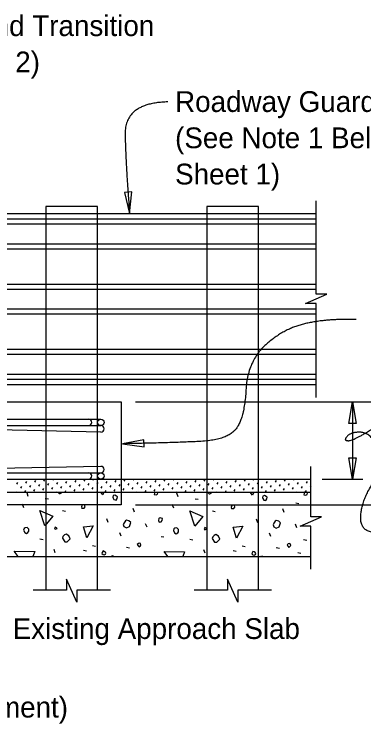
# Model space of a CAD drawing. Extents: x 0 to 41.1, y 0 to 26.
# Drawn here: x 32.17 to 35.56, y 8.63 to 15.52 of the extents above; entities that cross this region are included whole.
import ezdxf

# ---------------------------------------------------------------- set-up
doc = ezdxf.new("R2010")
doc.units = 0
for name, color, linetype in [('Dimension', 7, 'Continuous'), ('Miscellaneous', 7, 'Continuous'), ('Rebar', 7, 'Continuous'), ('TextStructures', 7, 'Continuous'), ('TrafBarrierConc', 7, 'Continuous')]:
    doc.layers.add(name, color=color, linetype=linetype)

# ---------------------------------------------------------------- blocks, each defined once
blk = doc.blocks.new('Terminator-Arrow')
at = {"layer": 'Dimension'}
blk.add_lwpolyline([(0, 0), (-0.00041, 0.000069), (-0.00041, -0.000069)], close=True, dxfattribs=at)

msp = doc.modelspace()

# ---------------------------------------------------------------- linework, layer by layer
at = {"layer": 'Dimension'}
for p, q in [((33.3449, 11.758), (36.4484, 11.758)), ((35.4495, 11.7581), (35.4495, 11.008)), ((35.1545, 11.008), (35.5492, 11.008)), ((33.3449, 10.758), (36.4484, 10.758))]:
    msp.add_line(p, q, dxfattribs=at)
for points in [[(33.2871, 13.5874), (33.3079, 13.7976), (33.2375, 13.7927)], [(33.2182, 11.3529), (33.427, 11.3211), (33.4259, 11.3916)]]:
    msp.add_lwpolyline(points, close=True, dxfattribs=at)
for points in [[(35.096, 11.8029), (35.096, 12.7141), (34.9927, 12.7141), (35.096, 12.7591), (35.1994, 12.8041), (35.096, 12.8041), (35.096, 13.713)], [(35.0443, 10.133), (35.0443, 10.5512), (34.941, 10.5512), (35.0443, 10.5962), (35.1476, 10.6412), (35.0443, 10.6412), (35.0443, 11.133)], [(33.1003, 9.9291), (32.775, 9.9291), (32.775, 9.8128), (32.6756, 10.0378), (32.6756, 9.9291), (32.3503, 9.9291)], [(34.6628, 9.9291), (34.3375, 9.9291), (34.3375, 9.8128), (34.2381, 10.0378), (34.2381, 9.9291), (33.9128, 9.9291)]]:
    msp.add_lwpolyline(points, dxfattribs=at)
for points in [[(33.6564, 14.6721), (33.2351, 14.6614), (33.2506, 14.042), (33.2871, 13.5874)], [(35.484, 12.5597), (35.1842, 12.5665), (34.7731, 12.4653), (34.4306, 12.1511), (34.4007, 11.5994), (34.2351, 11.3881), (33.6875, 11.3607), (33.2182, 11.3528)], [(35.6803, 10.4905), (35.5295, 10.4905), (35.5295, 10.7717), (35.7077, 11.0735), (35.7077, 11.293), (35.6049, 11.4645), (35.4335, 11.4645), (35.3582, 11.3822), (35.461, 11.3822), (35.6323, 11.492)]]:
    msp.add_open_spline(points, degree=2, dxfattribs=at)
at = {"layer": 'Miscellaneous'}
for p, q in [((27.9244, 13.588), (35.096, 13.588)), ((28.582, 13.5358), (35.096, 13.5358)), ((28.5832, 13.4876), (35.096, 13.4876)), ((28.5879, 13.2948), (35.096, 13.2948)), ((28.5891, 13.2465), (35.096, 13.2465)), ((28.5856, 12.9026), (35.096, 12.9026)), ((28.5844, 12.8543), (35.096, 12.8543)), ((28.575, 12.6134), (35.096, 12.6134)), ((28.5792, 12.6615), (35.096, 12.6615)), ((28.5891, 12.2695), (35.096, 12.2695)), ((28.5879, 12.2212), (35.096, 12.2212)), ((28.5817, 12.0284), (35.096, 12.0284)), ((27.9244, 11.9279), (35.096, 11.9279)), ((28.5827, 11.9802), (35.096, 11.9802)), ((32.1932, 10.9594), (32.2029, 10.9762)), ((32.2807, 10.9691), (32.2904, 10.9859)), ((32.3682, 10.9788), (32.3779, 10.9956)), ((32.4557, 10.9885), (32.4654, 11.0053)), ((32.4946, 10.9496), (32.5043, 10.9664)), ((32.5432, 10.9983), (32.5488, 11.008)), ((32.5821, 10.9594), (32.5918, 10.9762)), ((32.6696, 10.9691), (32.6793, 10.9859)), ((32.7571, 10.9788), (32.7668, 10.9956)), ((32.8446, 10.9885), (32.8543, 11.0053)), ((32.8835, 10.9496), (32.8932, 10.9664)), ((32.9321, 10.9983), (32.9377, 11.008)), ((32.971, 10.9594), (32.9807, 10.9762)), ((33.0585, 10.9691), (33.0682, 10.9859)), ((33.146, 10.9788), (33.1557, 10.9956)), ((33.2335, 10.9885), (33.2432, 11.0053)), ((33.2724, 10.9496), (33.2821, 10.9664)), ((33.321, 10.9983), (33.3266, 11.008)), ((33.3599, 10.9594), (33.3696, 10.9762)), ((33.4474, 10.9691), (33.4571, 10.9859)), ((33.5349, 10.9788), (33.5446, 10.9956)), ((33.6224, 10.9885), (33.6321, 11.0053)), ((33.6613, 10.9496), (33.671, 10.9664)), ((33.7099, 10.9983), (33.7156, 11.008)), ((33.7488, 10.9594), (33.7585, 10.9762)), ((33.8363, 10.9691), (33.846, 10.9859)), ((33.9238, 10.9788), (33.9336, 10.9956)), ((34.0113, 10.9885), (34.0211, 11.0053)), ((34.0502, 10.9496), (34.0599, 10.9664)), ((34.0988, 10.9983), (34.1045, 11.008)), ((34.1377, 10.9594), (34.1475, 10.9762)), ((34.2252, 10.9691), (34.235, 10.9859)), ((34.3127, 10.9788), (34.3225, 10.9956)), ((34.4002, 10.9885), (34.41, 11.0053)), ((34.4391, 10.9496), (34.4489, 10.9664)), ((34.4877, 10.9983), (34.4934, 11.008)), ((34.5266, 10.9594), (34.5364, 10.9762)), ((34.6141, 10.9691), (34.6239, 10.9859)), ((34.7016, 10.9788), (34.7114, 10.9956)), ((34.7892, 10.9885), (34.7989, 11.0053)), ((34.828, 10.9496), (34.8378, 10.9664)), ((34.8767, 10.9983), (34.8823, 11.008)), ((34.9155, 10.9594), (34.9253, 10.9762)), ((35.0031, 10.9691), (35.0128, 10.9859)), ((32.1899, 10.883), (32.1932, 10.8887)), ((32.2321, 10.9205), (32.2418, 10.9373)), ((32.2718, 10.883), (32.2807, 10.8984)), ((32.3196, 10.9302), (32.3293, 10.947)), ((32.3585, 10.8913), (32.3682, 10.9081)), ((32.4071, 10.9399), (32.4168, 10.9567)), ((32.446, 10.901), (32.4557, 10.9178)), ((32.5335, 10.9108), (32.5432, 10.9275)), ((32.5788, 10.883), (32.5821, 10.8887)), ((32.621, 10.9205), (32.6307, 10.9373)), ((32.6607, 10.883), (32.6696, 10.8984)), ((32.7085, 10.9302), (32.7182, 10.947)), ((32.7474, 10.8913), (32.7571, 10.9081)), ((32.796, 10.9399), (32.8057, 10.9567)), ((32.8349, 10.901), (32.8446, 10.9178)), ((32.9224, 10.9108), (32.9321, 10.9275)), ((32.9677, 10.883), (32.971, 10.8887)), ((33.0099, 10.9205), (33.0196, 10.9373)), ((33.0496, 10.883), (33.0585, 10.8984)), ((33.0974, 10.9302), (33.1071, 10.947)), ((33.1363, 10.8913), (33.146, 10.9081)), ((33.1849, 10.9399), (33.1946, 10.9567)), ((33.2238, 10.901), (33.2335, 10.9178)), ((33.3113, 10.9108), (33.321, 10.9275)), ((33.3566, 10.883), (33.3599, 10.8887)), ((33.3988, 10.9205), (33.4085, 10.9373)), ((33.4385, 10.883), (33.4474, 10.8984)), ((33.4863, 10.9302), (33.496, 10.947)), ((33.5252, 10.8913), (33.5349, 10.9081)), ((33.5738, 10.9399), (33.5835, 10.9567)), ((33.6127, 10.901), (33.6224, 10.9178)), ((33.7002, 10.9108), (33.7099, 10.9275)), ((33.7455, 10.883), (33.7488, 10.8887)), ((33.7877, 10.9205), (33.7974, 10.9373)), ((33.8274, 10.883), (33.8363, 10.8984)), ((33.8752, 10.9302), (33.8849, 10.947)), ((33.9141, 10.8913), (33.9238, 10.9081)), ((33.9627, 10.9399), (33.9724, 10.9567)), ((34.0016, 10.901), (34.0113, 10.9178)), ((34.0891, 10.9108), (34.0988, 10.9275)), ((34.1344, 10.883), (34.1377, 10.8887)), ((34.1766, 10.9205), (34.1863, 10.9373)), ((34.2163, 10.883), (34.2252, 10.8984)), ((34.2641, 10.9302), (34.2738, 10.947)), ((34.303, 10.8913), (34.3127, 10.9081)), ((34.3516, 10.9399), (34.3614, 10.9567)), ((34.3905, 10.901), (34.4002, 10.9178)), ((34.478, 10.9108), (34.4877, 10.9275)), ((34.5234, 10.883), (34.5266, 10.8887)), ((34.5655, 10.9205), (34.5753, 10.9373)), ((34.6052, 10.883), (34.6141, 10.8984)), ((34.653, 10.9302), (34.6628, 10.947)), ((34.6919, 10.8913), (34.7016, 10.9081)), ((34.7405, 10.9399), (34.7503, 10.9567)), ((34.7794, 10.901), (34.7892, 10.9178)), ((34.8669, 10.9108), (34.8767, 10.9275)), ((34.9123, 10.883), (34.9155, 10.8887)), ((34.9544, 10.9205), (34.9642, 10.9373)), ((34.9941, 10.883), (35.0031, 10.8984)), ((35.0419, 10.9302), (35.0479, 10.9405)), ((32.3042, 10.8413), (32.2919, 10.8749)), ((32.4686, 10.8219), (32.5005, 10.8184)), ((33.7573, 10.8378), (33.745, 10.8714)), ((32.2618, 10.7317), (32.2477, 10.7671)), ((33.7149, 10.7282), (33.7008, 10.7636)), ((33.9217, 10.8184), (33.9536, 10.8148)), ((34.8995, 10.7784), (34.9296, 10.7731)), ((32.6366, 10.7035), (32.6649, 10.6964)), ((33.3348, 10.6876), (33.3207, 10.7229)), ((34.0897, 10.6999), (34.118, 10.6929)), ((34.788, 10.684), (34.7738, 10.7194)), ((33.0785, 10.5868), (33.0644, 10.6221)), ((34.5316, 10.5833), (34.5175, 10.6186)), ((33.4568, 10.5408), (33.4427, 10.5762)), ((34.9099, 10.5373), (34.8958, 10.5726)), ((33.204, 10.4542), (33.1917, 10.4878)), ((34.6571, 10.4507), (34.6448, 10.4843)), ((32.4174, 10.4277), (32.4474, 10.4224)), ((33.5947, 10.4524), (33.6195, 10.4489)), ((33.8705, 10.4242), (33.9005, 10.4189)), ((34.9749, 10.4212), (35.005, 10.4159)), ((32.9265, 10.3641), (32.9548, 10.357)), ((33.2571, 10.3481), (33.2871, 10.3428)), ((34.3796, 10.3605), (34.4079, 10.3534)), ((34.7102, 10.3446), (34.7402, 10.3393)), ((32.5659, 10.2933), (32.5535, 10.3269)), ((32.8399, 10.3199), (32.8682, 10.3128)), ((34.019, 10.2898), (34.0066, 10.3234)), ((34.293, 10.3163), (34.3213, 10.3093)), ((34.9187, 10.2951), (34.9488, 10.2898))]:
    msp.add_line(p, q, dxfattribs=at)
for points in [[(32.9753, 9.9291), (32.9753, 13.6579), (32.4753, 13.6579), (32.4753, 9.9291)], [(34.5378, 9.9291), (34.5378, 13.6579), (34.0378, 13.6579), (34.0378, 9.9291)], [(32.5956, 10.883), (32.5977, 10.8767), (32.6048, 10.8696)], [(32.6048, 10.8696), (32.6118, 10.8696), (32.626, 10.8767), (32.6281, 10.883)], [(33.0273, 10.8573), (33.0077, 10.883)], [(33.0369, 10.883), (33.0273, 10.8573)], [(33.1263, 10.8254), (33.1351, 10.8095), (33.1563, 10.806), (33.1651, 10.8219), (33.1687, 10.836), (33.1598, 10.8449), (33.1439, 10.8537), (33.128, 10.8484), (33.1227, 10.8325), (33.1263, 10.8254)], [(33.5258, 10.8608), (33.5452, 10.8555), (33.5576, 10.8643), (33.5594, 10.8767), (33.5558, 10.8802), (33.5503, 10.883)], [(33.5289, 10.883), (33.5275, 10.8732), (33.5258, 10.8608)], [(34.0475, 10.883), (34.0508, 10.8732), (34.0579, 10.8661)], [(34.0579, 10.8661), (34.0649, 10.8661), (34.0791, 10.8732), (34.0823, 10.883)], [(34.4804, 10.8537), (34.4581, 10.883)], [(34.4913, 10.883), (34.4804, 10.8537)], [(34.5794, 10.8219), (34.5882, 10.806), (34.6094, 10.8025), (34.6182, 10.8184), (34.6218, 10.8325), (34.6129, 10.8413), (34.597, 10.8502), (34.5811, 10.8449), (34.5758, 10.829), (34.5794, 10.8219)], [(34.9789, 10.8573), (34.9983, 10.852), (35.0107, 10.8608), (35.0125, 10.8732), (35.0089, 10.8767), (34.9964, 10.883)], [(34.9893, 10.883), (34.9824, 10.882), (34.9806, 10.8696), (34.9789, 10.8573)], [(32.824, 10.7282), (32.8452, 10.7282), (32.8558, 10.7388), (32.8505, 10.7583), (32.8275, 10.76), (32.824, 10.7494), (32.8187, 10.7406), (32.824, 10.7282), (32.8204, 10.7317)], [(34.2771, 10.7247), (34.2983, 10.7247), (34.3089, 10.7353), (34.3036, 10.7547), (34.2806, 10.7565), (34.2771, 10.7459), (34.2718, 10.7371), (34.2771, 10.7247), (34.2735, 10.7282)], [(32.4651, 10.5567), (32.4174, 10.7035), (32.5429, 10.6487), (32.4651, 10.5567)], [(33.9182, 10.5532), (33.8705, 10.6999), (33.996, 10.6451), (33.9182, 10.5532)], [(33.5664, 10.608), (33.5753, 10.5921), (33.5947, 10.5939), (33.6035, 10.6062), (33.6053, 10.6257), (33.5929, 10.631), (33.5841, 10.6328), (33.5735, 10.6292), (33.57, 10.6257), (33.5664, 10.608)], [(32.8717, 10.4401), (32.8381, 10.5444), (32.9318, 10.5567), (32.8717, 10.4401)], [(33.2323, 10.5497), (33.2553, 10.5373), (33.2853, 10.5497), (33.2977, 10.5868), (33.28, 10.6045), (33.2571, 10.6098), (33.2465, 10.6027), (33.2341, 10.5833), (33.2252, 10.5673), (33.2323, 10.5497)], [(34.3248, 10.4365), (34.2912, 10.5408), (34.3849, 10.5532), (34.3248, 10.4365)], [(34.6854, 10.5461), (34.7084, 10.5338), (34.7385, 10.5461), (34.7508, 10.5833), (34.7332, 10.6009), (34.7102, 10.6062), (34.6996, 10.5992), (34.6872, 10.5797), (34.6783, 10.5638), (34.6854, 10.5461)], [(32.2583, 10.5125), (32.2689, 10.4913), (32.2866, 10.4807), (32.3007, 10.4913), (32.3078, 10.5019), (32.3078, 10.5232), (32.2919, 10.5391), (32.2724, 10.5373), (32.2636, 10.5285), (32.2583, 10.5125)], [(32.5641, 10.5214), (32.5835, 10.5302), (32.5765, 10.5373), (32.5641, 10.5426), (32.5588, 10.5302), (32.5641, 10.5214)], [(33.7114, 10.509), (33.722, 10.4878), (33.7397, 10.4772), (33.7538, 10.4878), (33.7609, 10.4984), (33.7609, 10.5196), (33.745, 10.5355), (33.7255, 10.5338), (33.7167, 10.5249), (33.7114, 10.509)], [(34.0172, 10.5178), (34.0367, 10.5267), (34.0296, 10.5338), (34.0172, 10.5391), (34.0119, 10.5267), (34.0172, 10.5178)], [(32.6348, 10.4365), (32.6578, 10.3994), (32.6808, 10.4012), (32.6896, 10.41), (32.7091, 10.4295), (32.6967, 10.4595), (32.6719, 10.4737), (32.6543, 10.4666), (32.6401, 10.4524), (32.6348, 10.4365)], [(34.0879, 10.433), (34.1109, 10.3959), (34.1339, 10.3976), (34.1427, 10.4065), (34.1622, 10.4259), (34.1498, 10.456), (34.125, 10.4701), (34.1074, 10.463), (34.0932, 10.4489), (34.0879, 10.433)], [(33.3684, 10.3605), (33.379, 10.3499), (33.3896, 10.357), (33.3967, 10.3676), (33.3932, 10.3853), (33.3843, 10.387), (33.372, 10.3853), (33.3614, 10.3747), (33.3684, 10.3605)], [(34.8215, 10.357), (34.8321, 10.3464), (34.8428, 10.3534), (34.8498, 10.3641), (34.8463, 10.3817), (34.8374, 10.3835), (34.8251, 10.3817), (34.8145, 10.3711), (34.8215, 10.357)], [(32.2071, 10.258), (32.1681, 10.3093), (32.3679, 10.3075), (32.3494, 10.258)], [(33.029, 10.2757), (33.0414, 10.2739), (33.0538, 10.2792), (33.0573, 10.2898), (33.052, 10.2986), (33.0414, 10.3057), (33.029, 10.311), (33.022, 10.2969), (33.0184, 10.2863), (33.029, 10.2757)], [(33.1106, 10.258), (33.1139, 10.2686), (33.1406, 10.258)], [(33.6575, 10.258), (33.6212, 10.3057), (33.821, 10.3039), (33.8038, 10.258)], [(34.4821, 10.2721), (34.4945, 10.2704), (34.5069, 10.2757), (34.5104, 10.2863), (34.5051, 10.2951), (34.4945, 10.3022), (34.4821, 10.3075), (34.4751, 10.2933), (34.4715, 10.2827), (34.4821, 10.2721)], [(34.5648, 10.258), (34.567, 10.2651), (34.5848, 10.258)]]:
    msp.add_lwpolyline(points, dxfattribs=at)
at = {"layer": 'Rebar'}
for p, q in [((29.3726, 11.5913), (33.0081, 11.5913)), ((29.3726, 11.5288), (33.0081, 11.5288)), ((33.0081, 11.4664), (30.2059, 11.5288)), ((33.0081, 11.1329), (30.2059, 11.0705)), ((29.3726, 11.0705), (33.0081, 11.0705)), ((29.3726, 11.008), (33.0081, 11.008))]:
    msp.add_line(p, q, dxfattribs=at)
for centre in [(33.0081, 11.56), (33.0081, 11.0392)]:
    msp.add_circle(centre, 0.0312, dxfattribs=at)
for centre in [(32.8878, 11.5601), (33.0081, 11.4976), (33.0081, 11.4976), (33.0081, 11.1017), (32.8878, 11.0393)]:
    msp.add_arc(centre, 0.0312, 270, 90, dxfattribs=at)
at = {"layer": 'TrafBarrierConc'}
for p, q in [((27.186, 11.758), (33.2059, 11.758)), ((33.2059, 11.758), (33.2059, 11.008)), ((29.9154, 11.008), (35.0443, 11.008)), ((29.9154, 10.883), (35.0495, 10.883)), ((27.206, 10.258), (35.0443, 10.258))]:
    msp.add_line(p, q, dxfattribs=at)
msp.add_lwpolyline([(33.2059, 11.758), (33.2059, 10.758), (30.2059, 10.758), (30.2059, 11.008)], dxfattribs=at)

# ---------------------------------------------------------------- block references
at = {"layer": 'Dimension', "xscale": 506.349, "yscale": -512.1577380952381}
for p, rotation in [((35.449, 11.7579), 90), ((35.4493, 11.0078), -90)]:
    msp.add_blockref('Terminator-Arrow', p, dxfattribs=dict(at, rotation=rotation))

# ---------------------------------------------------------------- texts
at = {"layer": 'Dimension'}
for s, p in [('Railing End Transition ', (30.889, 15.3116)), ('(See Note 2)', (30.889, 14.9596)), ('Roadway Guardrail Transition', (33.7281, 14.5745)), ('(See Note 1 Below & Note 1,', (33.7281, 14.2225)), ('Sheet 1)', (33.7281, 13.8705)), ('Dowel Bars 4L (10" Embedment)', (28.7577, 8.6934))]:
    msp.add_text(s, height=0.2016, dxfattribs=at).set_placement(p)
at = {"layer": 'TextStructures'}
msp.add_text('Existing Approach Slab', height=0.2016, dxfattribs=at).set_placement((32.1524, 9.4565))

doc.saveas('drawing.dxf')
